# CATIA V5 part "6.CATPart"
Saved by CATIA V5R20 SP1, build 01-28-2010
Part number: 6
Publications: "D", "C", "Droite.1", "E", "Droite.2", "Droite.3", "Droite.4", "Droite.5", "Droite.6", "Plan.1", "Droite.8"
Bounding box of the stored display mesh (mm): x -20 to 20, y 16.641 to 76.611, z 24.962 to 34.8
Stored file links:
  F:\TRAV\IAO\Exercice IAO\Catia\6.CATPart
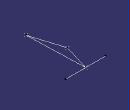
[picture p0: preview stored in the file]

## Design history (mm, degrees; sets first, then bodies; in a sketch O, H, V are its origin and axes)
Body1 (main body)
  Point1 "E": stored without definition
  Point2 "E": stored without definition
  Point3 "B": stored without definition
  Point4 "B": stored without definition
  DatumCurve1
  Sketch1 on yz-plane, origin (0, 0, 0), H (0, 1, 0), V (0, 0, 1)
    circle A1 centre (16.641, 24.9615) radius 50
    point P1 (16.641, 24.9615)
    reference projected point E1 (16.641, 24.9615) from Point1
    circle A2 centre (16.641, 24.9615) radius 60
    point P2 (16.641, 24.9615)
    reference projected point E2 (16.641, 24.9615) from Point2
    circle A3 centre (47.9625, -14.128) radius 50
    point P3 (47.9625, -14.128)
    reference projected point E3 (47.9625, -14.128) from Point4
    reference projected circle E4 centre (47.9625, -14.128) radius 50 from edge of DatumCurve1
    point P4 (76.6113, 26.8506)
    point P5 (1.7241, -33.1546)
    circle A4 centre (76.6113, 26.8506) radius 20
    point P6 (58.2591, 34.8003)
    point P7 (90.3796, 12.3443)
    radius A4 = 20
    coincidence: P1 E1, P2 E2, P3 E3, A3 E4, A3 P4, A2 P4, A3 P5, A2 P5, A3 P6, A4 P6, A3 P7, A4 P7
  Point5 "D": (0, 0, 0), relative to Sketch1.P6
  Point6 "C": (0, 0, 0), relative to Sketch1.P4
  Point7 "E": stored without definition
  Point8 "E": (0, 0, 0), relative to Point7
  Line1: type PtDir, RefPoint Point8, Direction yz-plane, Start -20, End 20
  Line2: type PtDir, RefPoint Point5, Direction yz-plane, Start -20, End 20
  Line3: type PtDir, RefPoint Point6, Direction yz-plane, Start -20, End 20
  Line4: type PtPt, FirstPoint Point8, SecondPoint Point5
  Line5: type PtPt, FirstPoint Point5, SecondPoint Point6
  Line6: type PtPt, FirstPoint Point6, SecondPoint Point8
  Plane1: type Offset, RefPlane yz-plane, Offset 0
  Line7: stored without definition
  Line8: type PtDir, RefPoint Point6, Direction Line7, Start -20, End 20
